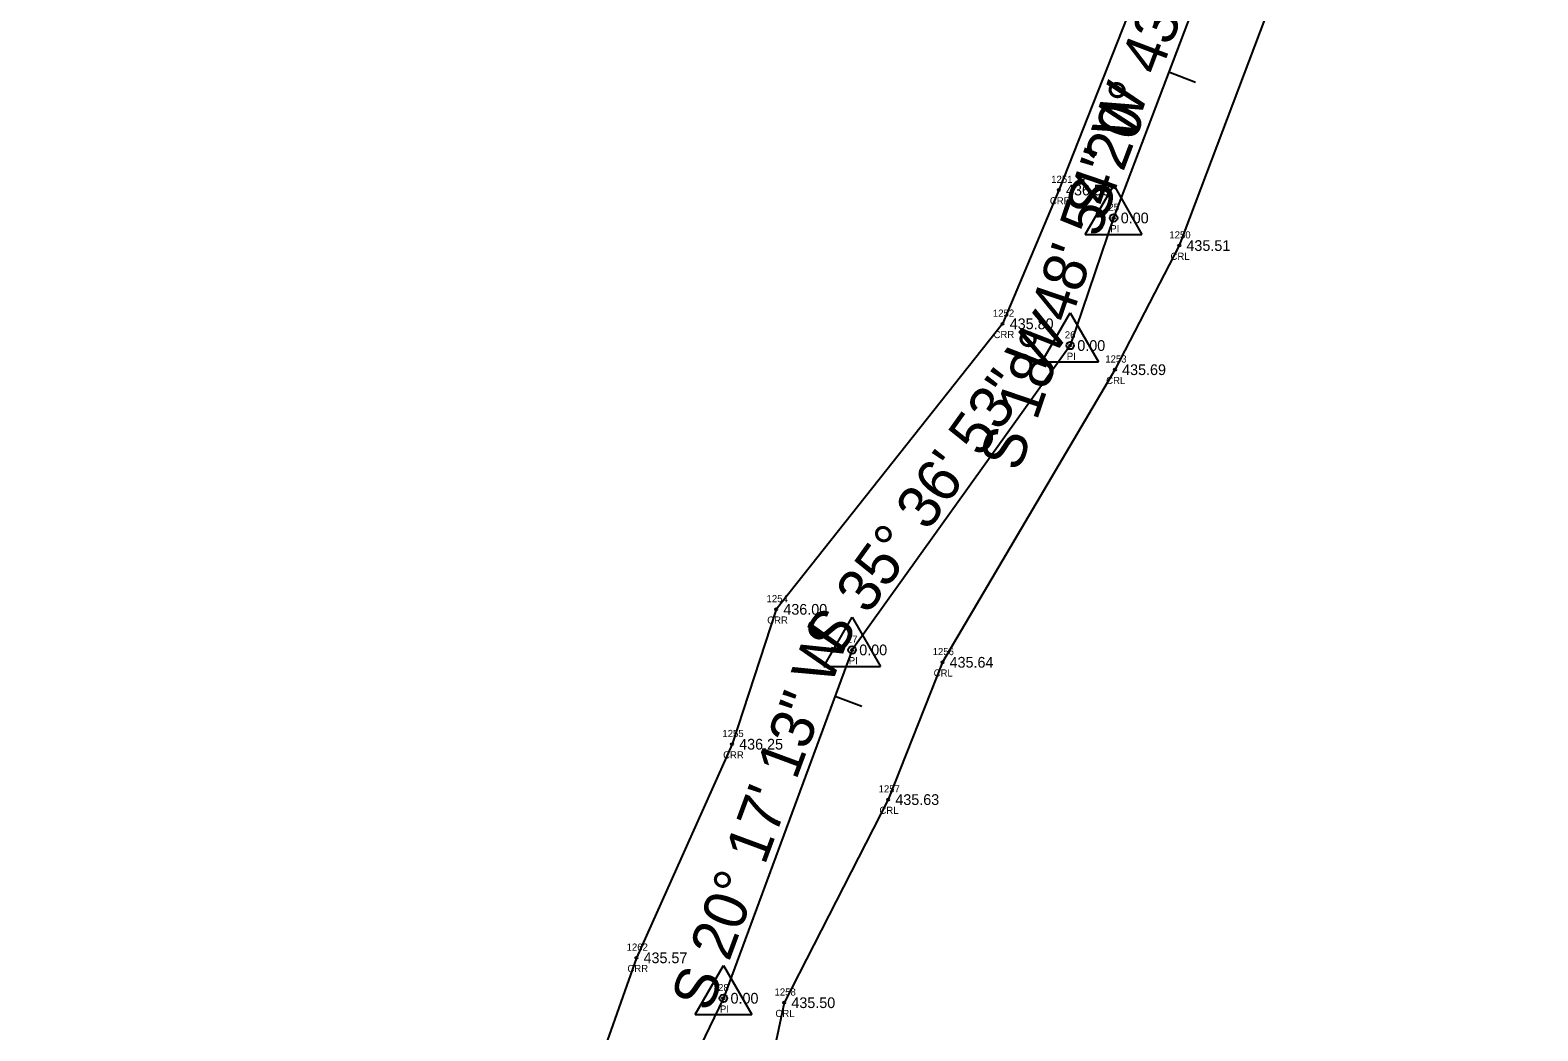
# Model space of a CAD drawing. Extents: x 1611865 to 1617004, y 775289 to 778546.
# Drawn here: x 1614423.2 to 1614634.1, y 777809.8 to 777949.8 of the extents above; entities that cross this region are included whole.
import ezdxf

# ---------------------------------------------------------------- set-up
doc = ezdxf.new("R2010")
doc.units = 0
for name, color, linetype in [('Default', 7, 'Continuous'), ('RD_EX_H2O', 7, 'Continuous'), ('RD_EX_H2O_txCode', 7, 'Continuous'), ('RD_EX_TX_H2O_ELEV', 7, 'Continuous'), ('RD_HC_Cl', 7, 'Continuous'), ('RD_HC_Data', 7, 'Continuous'), ('RD_HC_Data_Tic', 7, 'Continuous'), ('RD_HC_Survey_ELEV', 7, 'Continuous'), ('RD_HC_txCode', 7, 'Continuous'), ('RD_SMD_Locator', 7, 'Continuous')]:
    doc.layers.add(name, color=color, linetype=linetype)

msp = doc.modelspace()

# ---------------------------------------------------------------- linework, layer by layer
at = {"layer": 'Default'}
for p, q in [((1614594.16, 777974.77), (1614574.77, 777923.55)), ((1614574.77, 777923.55), (1614568.69, 777905.7)), ((1614568.69, 777905.7), (1614538.18, 777863.11)), ((1614538.18, 777863.11), (1614520.17, 777814.37)), ((1614520.17, 777814.37), (1614487, 777745.62))]:
    msp.add_line(p, q, dxfattribs=at)
at = {"layer": 'RD_EX_H2O'}
for points in [[(1614634.13, 778230.42), (1614629.46, 778175.6), (1614612.2, 778126.55), (1614606.67, 778108.17), (1614610.57, 778089.24), (1614615.98, 778055.09), (1614603.68, 778033.92), (1614586.84, 777977.49), (1614567.11, 777927.46), (1614559.23, 777908.74), (1614527.56, 777868.79), (1614521.38, 777849.92), (1614508, 777820.03), (1614493.75, 777779.64), (1614479.27, 777749.87), (1614469.02, 777727.63), (1614464.37, 777721.67), (1614444.52, 777689.77), (1614435.76, 777671.49), (1614423.17, 777629.21)], [(1614612.84, 778001.09), (1614602.8, 777969.59), (1614583.96, 777919.69), (1614574.96, 777902.32), (1614550.82, 777861.38), (1614543.23, 777842.17), (1614528.68, 777813.75), (1614526.1, 777801.65), (1614517.13, 777789.52), (1614510.38, 777774.58), (1614495.52, 777745.97), (1614480.57, 777714.78), (1614474.46, 777705.96), (1614477.93, 777705.13), (1614481.15, 777703.4), (1614481.27, 777700.99), (1614480.97, 777699.74), (1614478.44, 777696.16), (1614475.82, 777697.62), (1614468.32, 777689.25), (1614463.06, 777676.24), (1614459.87, 777668.19), (1614440.89, 777623.61)]]:
    msp.add_lwpolyline(points, dxfattribs=at)
at = {"layer": 'RD_HC_Cl'}
for p, q in [((1614594.16, 777974.77), (1614574.77, 777923.55)), ((1614574.77, 777923.55), (1614568.69, 777905.7)), ((1614568.69, 777905.7), (1614538.18, 777863.11)), ((1614538.18, 777863.11), (1614520.17, 777814.37)), ((1614520.17, 777814.37), (1614487, 777745.62))]:
    msp.add_line(p, q, dxfattribs=at)
at = {"layer": 'RD_HC_Data'}
for p, q in [((1614570.8, 777921.26), (1614574.78, 777928.14)), ((1614574.78, 777928.14), (1614578.74, 777921.26)), ((1614570.8, 777921.26), (1614578.74, 777921.26)), ((1614564.72, 777903.41), (1614568.69, 777910.29)), ((1614568.69, 777910.29), (1614572.66, 777903.41)), ((1614564.72, 777903.41), (1614572.66, 777903.41)), ((1614534.21, 777860.81), (1614538.18, 777867.69)), ((1614538.18, 777867.69), (1614542.15, 777860.81)), ((1614534.21, 777860.81), (1614542.15, 777860.81)), ((1614516.2, 777812.08), (1614520.17, 777818.96)), ((1614520.17, 777818.96), (1614524.14, 777812.08)), ((1614516.2, 777812.08), (1614524.14, 777812.08))]:
    msp.add_line(p, q, dxfattribs=at)
for centre in [(1614574.77, 777923.55), (1614568.69, 777905.7), (1614538.18, 777863.11), (1614520.17, 777814.37)]:
    msp.add_circle(centre, 0.529, dxfattribs=at)
at = {"layer": 'RD_HC_Data_Tic'}
for p, q in [((1614582.51, 777943.99), (1614586.25, 777942.57)), ((1614535.79, 777856.64), (1614539.54, 777855.25))]:
    msp.add_line(p, q, dxfattribs=at)
at = {"layer": 'RD_SMD_Locator'}
for centre in [(1614567.11, 777927.46), (1614574.77, 777923.55), (1614583.96, 777919.69), (1614559.23, 777908.74), (1614568.69, 777905.7), (1614574.96, 777902.32), (1614527.56, 777868.79), (1614538.18, 777863.11), (1614550.82, 777861.38), (1614521.38, 777849.92), (1614543.23, 777842.17), (1614508, 777820.03), (1614520.17, 777814.37), (1614528.68, 777813.75)]:
    msp.add_circle(centre, 0.15, dxfattribs=at)

# ---------------------------------------------------------------- texts
at = {"layer": 'RD_EX_H2O_txCode'}
for s, p in [('1251', (1614566.04, 777928.46)), ('CRR', (1614565.85, 777925.46)), ('1250', (1614582.57, 777920.69)), ('CRL', (1614582.73, 777917.69)), ('1252', (1614557.88, 777909.74)), ('CRR', (1614557.97, 777906.74)), ('1253', (1614573.61, 777903.32)), ('CRL', (1614573.73, 777900.32)), ('1254', (1614526.21, 777869.79)), ('CRR', (1614526.3, 777866.79)), ('1256', (1614549.45, 777862.38)), ('CRL', (1614549.59, 777859.38)), ('1255', (1614520.03, 777850.92)), ('CRR', (1614520.13, 777847.92)), ('1257', (1614541.89, 777843.17)), ('CRL', (1614542, 777840.17)), ('1262', (1614506.63, 777821.03)), ('CRR', (1614506.74, 777818.03)), ('1258', (1614527.33, 777814.75)), ('CRL', (1614527.45, 777811.75))]:
    msp.add_text(s, height=1, dxfattribs=at).set_placement(p)
at = {"layer": 'RD_EX_TX_H2O_ELEV'}
for s, p in [('436.50', (1614568.11, 777926.71)), ('435.51', (1614584.96, 777918.94)), ('435.80', (1614560.23, 777907.99)), ('435.69', (1614575.96, 777901.57)), ('436.00', (1614528.56, 777868.04)), ('435.64', (1614551.82, 777860.63)), ('436.25', (1614522.38, 777849.17)), ('435.63', (1614544.23, 777841.42)), ('435.57', (1614509, 777819.28)), ('435.50', (1614529.68, 777813))]:
    msp.add_text(s, height=1.5, dxfattribs=at).set_placement(p)
at = {"layer": 'RD_HC_Data'}
for s, rotation, p in [('S 20%%d 43\' 41" W', 69.2721, (1614573.41, 777922.78)), ('S 18%%d 48\' 54" W', 71.185, (1614561.57, 777887.89)), ('S 35%%d 36\' 53" W', 54.3853, (1614535.98, 777861.75)), ('S 20%%d 17\' 13" W', 69.7132, (1614518.33, 777812.27))]:
    msp.add_text(s, height=6, rotation=rotation, dxfattribs=at).set_placement(p)
at = {"layer": 'RD_HC_Survey_ELEV'}
for p in [(1614575.77, 777922.8), (1614569.69, 777904.95), (1614539.18, 777862.36), (1614521.17, 777813.62)]:
    msp.add_text('0.00', height=1.5, dxfattribs=at).set_placement(p)
at = {"layer": 'RD_HC_txCode'}
for s, p in [('25', (1614574.04, 777924.55)), ('PI', (1614574.3, 777921.55)), ('26', (1614567.94, 777906.7)), ('PI', (1614568.22, 777903.7)), ('27', (1614537.45, 777864.11)), ('PI', (1614537.71, 777861.11)), ('28', (1614519.43, 777815.37)), ('PI', (1614519.69, 777812.37))]:
    msp.add_text(s, height=1, dxfattribs=at).set_placement(p)

doc.saveas('drawing.dxf')
